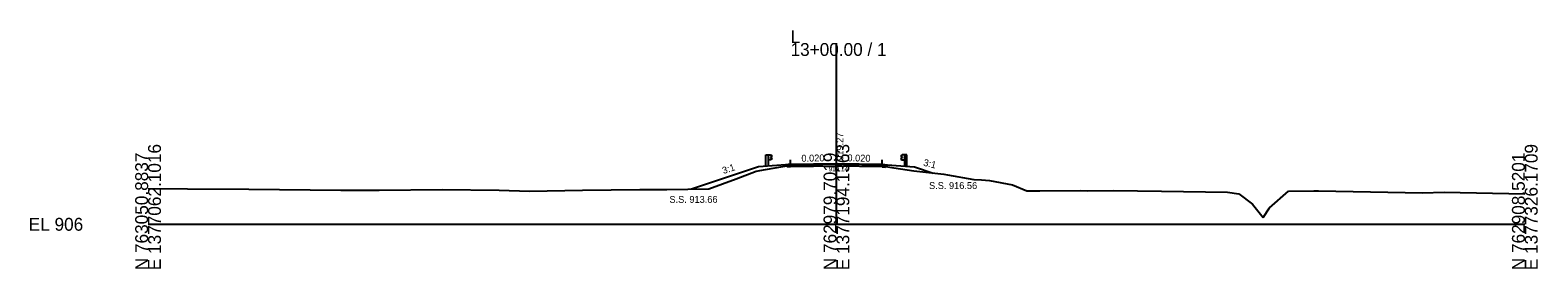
# Model space of a CAD drawing. Extents: x -26 to 303, y -10 to 6523.
# Drawn here: x -25.7 to 302.8, y 2990.3 to 3042.3 of the extents above; entities that cross this region are included whole.
import ezdxf

# ---------------------------------------------------------------- set-up
doc = ezdxf.new("R2010")
doc.units = 0
for name, color, linetype in [('Exist Cross Section Cell', 7, 'Continuous'), ('Exist XS Center Line Elevation Label', 7, 'Continuous'), ('Exist XS Ground Line', 7, 'Continuous'), ('Prop XS Ditch Slope Text', 7, 'Continuous'), ('Prop XS Dump Level', 7, 'Continuous'), ('Prop XS Elevation Labels', 7, 'Continuous'), ('Prop XS EOT Tick Mark', 7, 'Continuous'), ('Prop XS Finish Grade', 7, 'Continuous'), ('Prop XS Finish Grade Earthwork', 7, 'Continuous'), ('Prop XS Finish Grade Pavement', 7, 'Continuous'), ('Prop XS Guardrail', 7, 'Continuous'), ('Prop XS Pvmt Edge Slope', 7, 'Continuous'), ('Prop XS SE Text', 7, 'Continuous'), ('Prop XS Side Slope Text', 7, 'Continuous'), ('Prop XS SS Elevation Text', 7, 'Continuous'), ('Prop XS Subgrade Earthwork', 7, 'Continuous')]:
    doc.layers.add(name, color=color, linetype=linetype)

msp = doc.modelspace()

# ---------------------------------------------------------------- linework, layer by layer
at = {"layer": 'Exist Cross Section Cell'}
for p, q in [((150, 3000), (150, 3039.46)), ((0, 3000), (150, 3000)), ((150, 3000), (300, 3000))]:
    msp.add_line(p, q, dxfattribs=at)
at = {"layer": 'Exist XS Ground Line'}
for p, q in [((134.53, 3011.91), (139.97, 3012.85)), ((139.97, 3012.85), (143.1, 3012.96)), ((143.1, 3012.96), (149, 3013.15)), ((149, 3013.15), (150, 3013.14)), ((150, 3013.14), (152.49, 3013.09)), ((152.49, 3013.09), (158.57, 3012.96)), ((158.57, 3012.96), (162.52, 3012.31)), ((122.16, 3007.69), (128.17, 3009.93)), ((128.17, 3009.93), (132.48, 3011.57)), ((132.48, 3011.57), (134.53, 3011.91)), ((162.52, 3012.31), (166.87, 3011.66)), ((166.87, 3011.66), (170.12, 3011.27)), ((170.12, 3011.27), (173.38, 3010.88)), ((173.38, 3010.88), (174.21, 3010.75)), ((174.21, 3010.75), (179.96, 3009.76)), ((179.96, 3009.76), (181.64, 3009.65)), ((181.64, 3009.65), (183.37, 3009.55)), ((183.37, 3009.55), (188.34, 3008.59)), ((0, 3007.76), (8.58, 3007.7)), ((8.58, 3007.7), (21.96, 3007.64)), ((21.96, 3007.64), (42.01, 3007.46)), ((42.01, 3007.46), (47.53, 3007.43)), ((47.53, 3007.43), (50.36, 3007.44)), ((50.36, 3007.44), (64.12, 3007.57)), ((64.12, 3007.57), (76.53, 3007.46)), ((76.53, 3007.46), (83.13, 3007.21)), ((83.13, 3007.21), (94.66, 3007.41)), ((94.66, 3007.41), (107.18, 3007.61)), ((107.18, 3007.61), (113.06, 3007.6)), ((113.06, 3007.6), (122.16, 3007.69)), ((188.34, 3008.59), (191.47, 3007.32)), ((191.47, 3007.32), (194.32, 3007.32)), ((194.32, 3007.32), (203.11, 3007.35)), ((203.11, 3007.35), (204.72, 3007.26)), ((204.72, 3007.26), (210.39, 3007.33)), ((210.39, 3007.33), (220.82, 3007.2)), ((220.82, 3007.2), (235.23, 3006.98)), ((235.23, 3006.98), (237.7, 3006.6)), ((237.7, 3006.6), (240.68, 3004.4)), ((244.35, 3003.6), (248.5, 3007.2)), ((248.5, 3007.2), (254.03, 3007.25)), ((254.03, 3007.25), (254.37, 3007.25)), ((254.37, 3007.25), (255.05, 3007.25)), ((255.05, 3007.25), (277.7, 3006.86)), ((277.7, 3006.86), (282.42, 3006.98)), ((282.42, 3006.98), (300, 3006.61)), ((240.68, 3004.4), (242.96, 3001.46)), ((242.96, 3001.46), (244.35, 3003.6))]:
    msp.add_line(p, q, dxfattribs=at)
at = {"layer": 'Prop XS Dump Level'}
for p, q in [((140, 3013.07), (150, 3013.27)), ((150, 3013.27), (160, 3013.07))]:
    msp.add_line(p, q, dxfattribs=at)
at = {"layer": 'Prop XS EOT Tick Mark'}
for p, q in [((140, 3013.07), (140, 3014.07)), ((160, 3013.07), (160, 3014.07))]:
    msp.add_line(p, q, dxfattribs=at)
at = {"layer": 'Prop XS Finish Grade'}
for p, q in [((140, 3013.07), (138.9, 3012.98)), ((160, 3013.07), (161.1, 3012.98))]:
    msp.add_line(p, q, dxfattribs=at)
at = {"layer": 'Prop XS Finish Grade Earthwork'}
for p, q in [((137, 3012.83), (133, 3012.51)), ((138.9, 3012.98), (137, 3012.83)), ((161.1, 3012.98), (163, 3012.83)), ((163, 3012.83), (167, 3012.51)), ((133, 3012.51), (118.44, 3007.66)), ((167, 3012.51), (171.05, 3011.16))]:
    msp.add_line(p, q, dxfattribs=at)
at = {"layer": 'Prop XS Finish Grade Pavement'}
for p, q in [((140, 3013.07), (150, 3013.27)), ((150, 3013.27), (160, 3013.07))]:
    msp.add_line(p, q, dxfattribs=at)
at = {"layer": 'Prop XS Guardrail'}
for p, q in [((134.61, 3015.14), (135.11, 3015.14)), ((134.61, 3012.64), (134.61, 3015.14)), ((135.11, 3015.14), (135.61, 3015.14)), ((135.11, 3015.14), (135.11, 3012.64)), ((135.61, 3014), (135.11, 3014)), ((135.61, 3015.14), (135.9, 3014.94)), ((135.9, 3014.82), (135.61, 3014.62)), ((135.61, 3014.62), (135.61, 3014.52)), ((135.61, 3014.52), (135.9, 3014.32)), ((135.9, 3014.2), (135.61, 3014)), ((135.9, 3014.94), (135.93, 3014.88)), ((135.93, 3014.88), (135.9, 3014.82)), ((135.9, 3014.32), (135.93, 3014.26)), ((135.93, 3014.26), (135.9, 3014.2)), ((164.03, 3014.94), (164, 3014.88)), ((164, 3014.88), (164.03, 3014.82)), ((164.03, 3014.33), (164, 3014.27)), ((164, 3014.27), (164.03, 3014.21)), ((164.32, 3015.14), (164.03, 3014.94)), ((164.03, 3014.82), (164.32, 3014.62)), ((164.32, 3014.53), (164.03, 3014.33)), ((164.03, 3014.21), (164.32, 3014.01)), ((164.82, 3015.14), (164.32, 3015.14)), ((164.32, 3014.62), (164.32, 3014.53)), ((164.32, 3014.01), (164.82, 3014.01)), ((165.32, 3015.14), (164.82, 3015.14)), ((164.82, 3015.14), (164.82, 3012.64)), ((165.32, 3012.64), (165.32, 3015.14))]:
    msp.add_line(p, q, dxfattribs=at)
at = {"layer": 'Prop XS Pvmt Edge Slope'}
for p, q in [((140, 3013.07), (139.4, 3012.47)), ((160, 3013.07), (160.6, 3012.47))]:
    msp.add_line(p, q, dxfattribs=at)
at = {"layer": 'Prop XS Subgrade Earthwork'}
for p, q in [((139.4, 3012.47), (138.9, 3012.98)), ((150, 3012.69), (140, 3012.49)), ((160, 3012.49), (150, 3012.69)), ((160.6, 3012.47), (161.1, 3012.98)), ((140, 3012.49), (139.4, 3012.47)), ((160, 3012.49), (160.6, 3012.47))]:
    msp.add_line(p, q, dxfattribs=at)

# ---------------------------------------------------------------- texts
at = {"layer": 'Exist Cross Section Cell'}
for s, p in [('L', (140, 3039.46)), ('13+00.00 / 1', (140, 3036.66)), ('EL 906', (-26, 2998.6))]:
    msp.add_text(s, height=2.8, dxfattribs=at).set_placement(p)
for s, p in [('E 1377062.1016', (2.8, 2990)), ('E 1377194.1363', (152.8, 2990)), ('E 1377326.1709', (302.8, 2990)), ('N 763050.8837', (0, 2990)), ('N 762979.7019', (150, 2990)), ('N 762908.5201', (300, 2990))]:
    msp.add_text(s, height=2.8, rotation=90, dxfattribs=at).set_placement(p)
at = {"layer": 'Exist XS Center Line Elevation Label'}
msp.add_text('919.14', height=0.998, dxfattribs=at).set_placement((148.31, 3011.55))
at = {"layer": 'Prop XS Ditch Slope Text'}
msp.add_text('3:1', height=1.5, rotation=345.9638, dxfattribs=at).set_placement((168.82, 3012.79))
at = {"layer": 'Prop XS Dump Level'}
for p in [(137, 3012.79), (163, 3012.79)]:
    msp.add_text('Case1', height=0.04, dxfattribs=at).set_placement(p)
at = {"layer": 'Prop XS Elevation Labels'}
msp.add_text(' 919.27', height=1.5, rotation=90, dxfattribs=at).set_placement((151.5, 3013.27))
at = {"layer": 'Prop XS SE Text'}
for rotation, p in [(1.1458, (142.38, 3013.62)), (358.8542, (152.38, 3013.72))]:
    msp.add_text('0.020', height=1.5, rotation=rotation, dxfattribs=at).set_placement(p)
at = {"layer": 'Prop XS Side Slope Text'}
msp.add_text('3:1', height=1.5, rotation=18.4349, dxfattribs=at).set_placement((125.39, 3010.93))
at = {"layer": 'Prop XS SS Elevation Text'}
for s, p in [('S.S. 913.66', (113.61, 3004.67)), ('S.S. 916.56', (170.18, 3007.68))]:
    msp.add_text(s, height=1.5, dxfattribs=at).set_placement(p)

doc.saveas('drawing.dxf')
